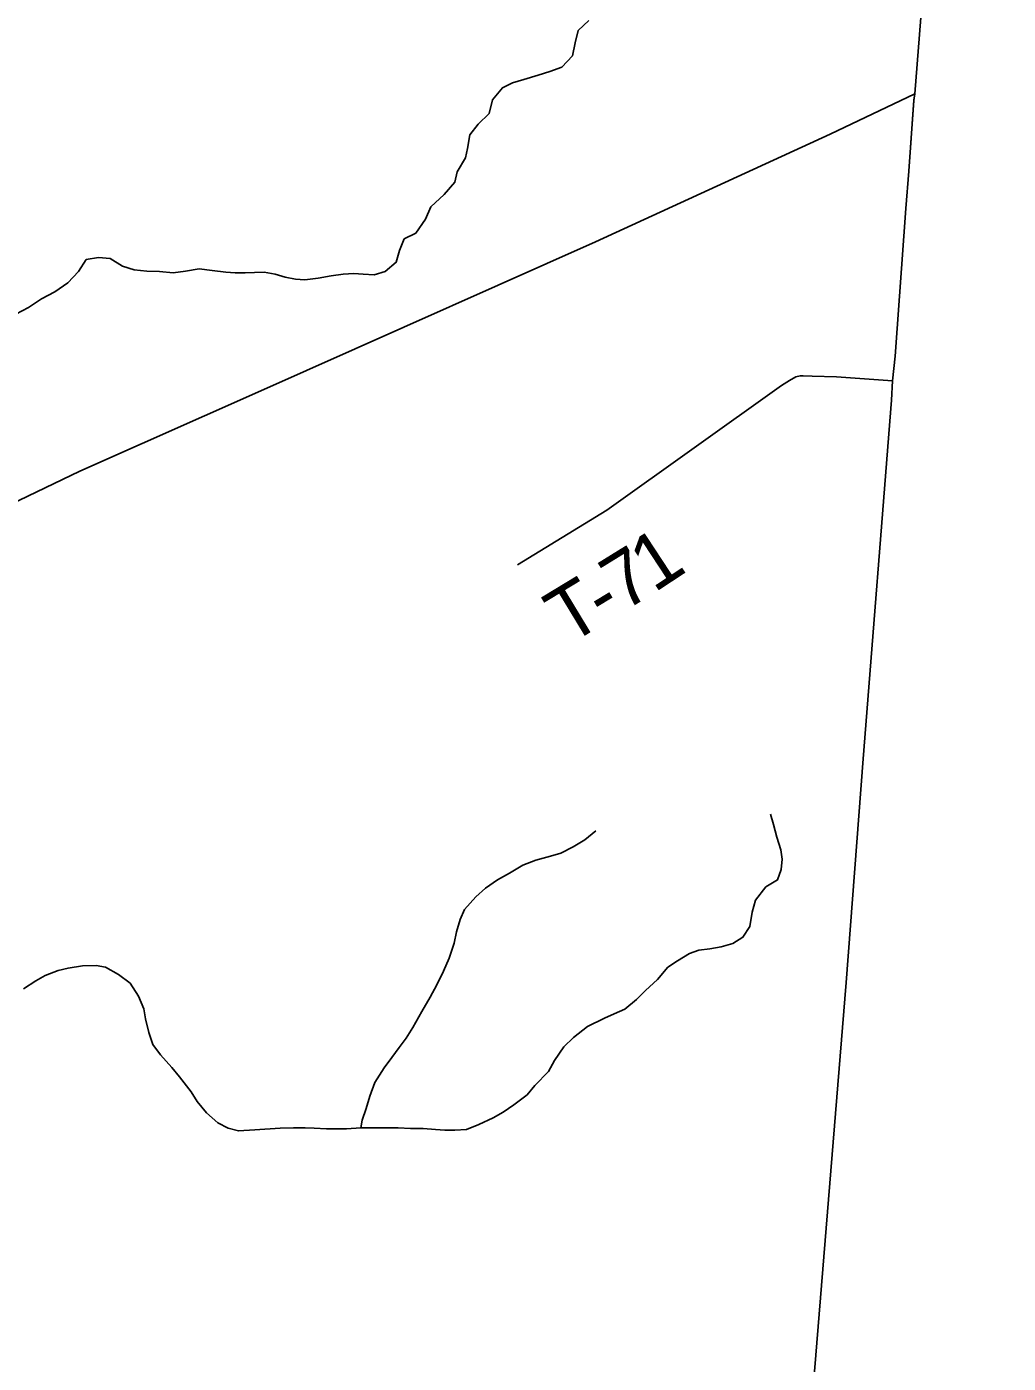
# Model space of a CAD drawing. Extents: x 1643459 to 2064572, y 425441 to 780708.
# Drawn here: x 1869026 to 1874344, y 587623 to 594862 of the extents above; entities that cross this region are included whole.
import ezdxf

# ---------------------------------------------------------------- set-up
doc = ezdxf.new("R2010")
doc.units = 0
for name, color, linetype in [('GM_X_City_Street', 7, 'Continuous'), ('GM_X_Interstate_Route', 7, 'Continuous'), ('GM_X_Major_River', 7, 'Continuous'), ('GM_X_Major_River_Text', 7, 'Continuous'), ('GM_X_Minor_Lake', 7, 'Continuous'), ('GM_X_Minor_River', 7, 'Continuous'), ('GM_X_US_Route', 7, 'Continuous'), ('RD_X_Text', 7, 'Continuous'), ('RD_X_Wall', 7, 'Continuous')]:
    doc.layers.add(name, color=color, linetype=linetype)

msp = doc.modelspace()

# ---------------------------------------------------------------- linework, layer by layer
at = {"layer": 'GM_X_City_Street'}
msp.add_lwpolyline([(1857189.7, 602061.2), (1860985.5, 601834), (1863982.7, 601657.3), (1866649.2, 601470.4), (1868960.6, 601322.8), (1873424.2, 600995.3), (1874343.7, 600929.7), (1873993.6, 596512.5), (1873944.4, 595854.7), (1873837.4, 594497.5), (1873832.6, 594463.2), (1873804.1, 594079), (1873789.2, 593877.9), (1873731.7, 593076.8), (1873716.7, 592943.7), (1873711.2, 592838.6), (1873557, 590896.5), (1873465.3, 589684.5), (1873078.1, 584937.7)], dxfattribs=at)
at = {"layer": 'GM_X_Interstate_Route'}
msp.add_lwpolyline([(1873078.1, 584937.7), (1873465.3, 589684.5), (1873557, 590896.5), (1873711.2, 592838.6), (1873716.7, 592943.7), (1873731.7, 593076.8), (1873789.2, 593877.9), (1873804.1, 594079), (1873832.6, 594463.2), (1873837.4, 594497.5), (1873944.4, 595854.7), (1873993.6, 596512.5), (1874343.7, 600929.7), (1873424.2, 600995.3), (1873573.5, 602796.9), (1873572.1, 602862.2), (1873574.2, 602927.5), (1873657.2, 604071.9), (1873746.1, 605342.8), (1873797.3, 606115.1), (1873820.8, 606443.6), (1873900.5, 607668.7), (1874002, 608977.1), (1874127.7, 610670.8)], dxfattribs=at)
at = {"layer": 'GM_X_Major_River_Text'}
msp.add_lwpolyline([(1871684.8, 591948.1), (1872168.2, 592242.7), (1873115.8, 592918.9), (1873158.1, 592946), (1873192.8, 592965.4), (1873216.4, 592971.4), (1873231.7, 592970.5), (1873280.7, 592968.8), (1873412.6, 592966.1), (1873716.7, 592943.7)], dxfattribs=at)
at = {"layer": 'GM_X_Minor_Lake'}
msp.add_lwpolyline([(1873075.7, 584913.1), (1873078.1, 584937.7), (1873465.2, 589684.5), (1873557, 590896.5), (1873711.2, 592838.6), (1873716.7, 592943.7), (1873731.7, 593076.8), (1873789.2, 593877.9), (1873804.1, 594079), (1873832.6, 594463.1), (1873837.4, 594497.5)], dxfattribs=at)
at = {"layer": 'GM_X_Minor_River'}
msp.add_lwpolyline([(1874127.7, 610670.8), (1874002, 608977.1), (1873900.5, 607668.7), (1873820.8, 606443.6), (1873797.3, 606115.1), (1873746.1, 605342.8), (1873657.2, 604071.9), (1873574.2, 602927.5), (1873572.1, 602862.2), (1873573.5, 602796.9), (1873424.2, 600995.3), (1874343.7, 600929.7), (1873993.6, 596512.5), (1873944.4, 595854.7), (1873837.4, 594497.5), (1873832.6, 594463.2), (1873804.1, 594079), (1873789.2, 593877.9), (1873731.7, 593076.8), (1873716.7, 592943.7), (1873711.2, 592838.6), (1873557, 590896.5), (1873465.3, 589684.5), (1873078.1, 584937.7)], dxfattribs=at)
at = {"layer": 'GM_X_US_Route'}
for points in [[(1868966, 593305.1), (1869036.3, 593340.5), (1869106.7, 593388), (1869179, 593425.4), (1869249.5, 593474.9), (1869306, 593536.5), (1869348.6, 593600.3), (1869414.7, 593611.7), (1869478.7, 593607.1), (1869544.2, 593564.3), (1869608.1, 593545.7), (1869676, 593537), (1869745.9, 593536.3), (1869819.9, 593529.6), (1869885.9, 593537), (1869960, 593550.3), (1870029.9, 593541.7), (1870103.8, 593532.9), (1870155.8, 593528.4), (1870209.7, 593527.9), (1870259.8, 593531.4), (1870311.8, 593532.9), (1870371.7, 593522.3), (1870425.5, 593505.8), (1870481.4, 593495.2), (1870533.3, 593490.7), (1870605.4, 593500), (1870675.5, 593513.4), (1870739.5, 593520.8), (1870797.6, 593524.3), (1870849.5, 593521.8), (1870907.5, 593517.2), (1870967.6, 593536.7), (1871028.1, 593586.3), (1871044.7, 593650.3), (1871071.2, 593712.2), (1871133.5, 593743.7), (1871186.2, 593819.4), (1871214.8, 593885.4), (1871287.4, 593952.9), (1871346.1, 594020.5), (1871358.6, 594076.5), (1871403.3, 594152.3), (1871413.7, 594202.4), (1871426.4, 594276.5), (1871471, 594334.2), (1871531.5, 594391.8), (1871550.2, 594465.8), (1871602.8, 594531.5), (1871657, 594557.1), (1871719.1, 594576.6), (1871797.4, 594599.9), (1871859.5, 594619.3), (1871925.7, 594642.8), (1871982.3, 594704.4), (1871996.9, 594774.5), (1872013.5, 594840.5), (1872072, 594896.1)], [(1869075.3, 589693.3), (1869125.4, 589723.4), (1869195.5, 589749.4), (1869249.6, 589763.5), (1869327.7, 589775.5), (1869401.8, 589777.4), (1869451.8, 589767.3), (1869523.8, 589729.2), (1869585.8, 589680.9), (1869631.8, 589610.6), (1869659.7, 589542.4), (1869669.6, 589488.2), (1869687.5, 589413.8), (1869709.4, 589349.6), (1869751.4, 589293.3), (1869811.3, 589225), (1869853.3, 589174.8), (1869917.2, 589092.5), (1869949.2, 589040.3), (1869999.1, 588980), (1870061.1, 588925.8), (1870117.1, 588895.6), (1870173.1, 588881.5), (1870261.3, 588887.5), (1870399.4, 588895.4), (1870471.5, 588897.4), (1870533.6, 588897.3), (1870583.6, 588895.3), (1870649.7, 588893.3), (1870757.8, 588893.2), (1870835.9, 588897.2), (1870972, 588897.1), (1871038.1, 588897), (1871104.2, 588895), (1871174.3, 588894.9), (1871240.3, 588888.9), (1871290.4, 588884.8), (1871344.4, 588884.8), (1871408.5, 588888.8), (1871474.6, 588916.8), (1871552.8, 588952.9), (1871606.9, 588983), (1871665, 589023.1), (1871737.2, 589077.2), (1871779.3, 589127.4), (1871853.5, 589203.7), (1871885.6, 589261.9), (1871935.8, 589336.1), (1871988, 589386.3), (1872064.1, 589446.5), (1872156.3, 589492.6), (1872208.4, 589514.6), (1872266.5, 589540.7), (1872328.7, 589592.8), (1872378.8, 589641), (1872443, 589701.2), (1872499.1, 589767.4), (1872551.3, 589801.5), (1872617.4, 589841.6), (1872667.5, 589859.6), (1872727.6, 589867.6), (1872787.6, 589877.6), (1872851.7, 589895.7), (1872905.8, 589929.8), (1872944, 589987.9), (1872956.1, 590066.2), (1872974.3, 590130.5), (1873030.4, 590202.7), (1873092.6, 590240.8), (1873112.7, 590297), (1873118.8, 590353.2), (1873110.9, 590403.4), (1873089, 590471.7), (1873071, 590540), (1873055.1, 590596.2)], [(1870835.9, 588897.2), (1870844, 588939.3), (1870864.1, 589003.5), (1870884.2, 589069.8), (1870912.4, 589144), (1870962.6, 589222.3), (1871004.7, 589278.5), (1871042.8, 589332.7), (1871081, 589382.8), (1871117.1, 589441), (1871167.3, 589527.3), (1871211.5, 589605.6), (1871247.6, 589671.8), (1871283.8, 589746.1), (1871313.9, 589816.3), (1871342.1, 589898.6), (1871354.2, 589958.8), (1871374.4, 590027.1), (1871398.5, 590081.3), (1871458.6, 590149.5), (1871510.8, 590195.7), (1871576.9, 590241.8), (1871641.1, 590277.9), (1871713.2, 590320), (1871783.3, 590348), (1871863.5, 590370.1), (1871919.5, 590386.1), (1871985.7, 590420.2), (1872049.8, 590458.3), (1872109.9, 590506.4)], [(1869009.2, 589651.2), (1869075.3, 589693.3)]]:
    msp.add_lwpolyline(points, dxfattribs=at)
at = {"layer": 'RD_X_Text'}
msp.add_lwpolyline([(1873837.4, 594497.5), (1873944.3, 595854.7), (1873993.6, 596512.5), (1874343.7, 600929.7)], dxfattribs=at)
at = {"layer": 'RD_X_Wall'}
for points in [[(1870326, 592904.2), (1870541.4, 592999.8), (1872108.2, 593696.9), (1873378.8, 594279.7), (1873837.4, 594497.5)], [(1862856.5, 589813.5), (1863732.6, 590172.9), (1864004.2, 590247.9), (1865252.4, 590610.9), (1865326.7, 590614.2), (1866865.2, 591313.4), (1868139.1, 591892.1), (1869313.7, 592455), (1870326, 592904.2)]]:
    msp.add_lwpolyline(points, dxfattribs=at)

# ---------------------------------------------------------------- texts
at = {"layer": 'GM_X_Major_River'}
for s, rotation, p in [('1', 33.31623, (1872424.4, 591792.9)), ('7', 31.726, (1872259.6, 591690.9)), ('T', 31.20629, (1871959.9, 591509)), ('-', 31.3114, (1872152.3, 591625.6))]:
    msp.add_text(s, height=300, rotation=rotation, dxfattribs=at).set_placement(p)

doc.saveas('drawing.dxf')
